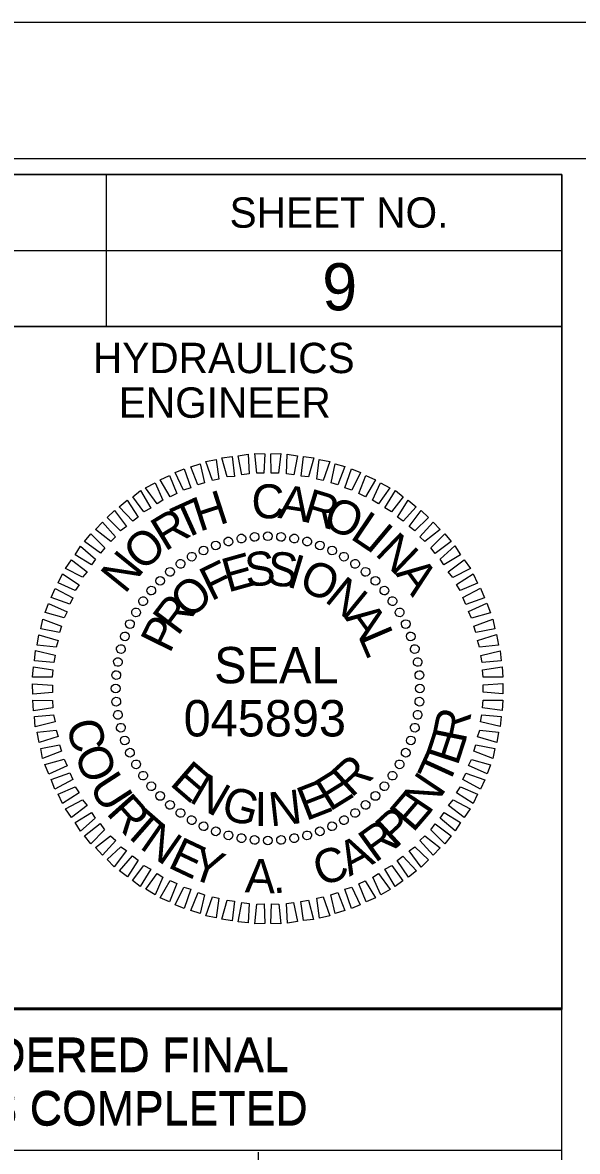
# Model space of a CAD drawing. Extents: x 1626113 to 1628102, y 900759 to 901859.
# Drawn here: x 1627691.2 to 1627782.5, y 901673.3 to 901859.2 of the extents above; entities that cross this region are included whole.
import ezdxf

# ---------------------------------------------------------------- set-up
doc = ezdxf.new("R2010")
doc.units = 0
for name, color, linetype in [('Default', 7, 'Continuous'), ('Sheet Cutting Line CELL', 7, 'Continuous'), ('Sheet Data Field CELL', 7, 'Continuous'), ('Sheet Plot Border Inside CELL', 7, 'Continuous'), ('Sheet Plot Border Outside CELL', 7, 'Continuous'), ('Sheet Profile CELL', 7, 'Continuous'), ('Sheet Profile Grid Major CELL', 7, 'Continuous'), ('Sheet Sticker Exception Certification CELL', 7, 'Continuous')]:
    doc.layers.add(name, color=color, linetype=linetype)

msp = doc.modelspace()

# ---------------------------------------------------------------- linework, layer by layer
at = {"layer": 'Default'}
for p, q in [((1627727.21, 901774.16), (1627727.21, 901774.16)), ((1627729.36, 901774.46), (1627729.36, 901774.46)), ((1627731.56, 901774.61), (1627731.56, 901774.61)), ((1627733.76, 901774.46), (1627733.76, 901774.46)), ((1627735.91, 901774.16), (1627735.91, 901774.16)), ((1627721.01, 901772.21), (1627721.01, 901772.21)), ((1627722.96, 901773.06), (1627722.96, 901773.06)), ((1627725.06, 901773.71), (1627725.06, 901773.71)), ((1627738.06, 901773.71), (1627738.06, 901773.71)), ((1627740.16, 901773.06), (1627740.16, 901773.06)), ((1627742.16, 901772.21), (1627742.16, 901772.21)), ((1627719.06, 901771.21), (1627719.06, 901771.21)), ((1627744.11, 901771.21), (1627744.11, 901771.21)), ((1627715.4, 901768.76), (1627715.4, 901768.76)), ((1627717.21, 901770.01), (1627717.21, 901770.01)), ((1627745.91, 901770.06), (1627745.91, 901770.06)), ((1627747.71, 901768.71), (1627747.71, 901768.71)), ((1627713.81, 901767.21), (1627713.81, 901767.21)), ((1627749.26, 901767.26), (1627749.26, 901767.26)), ((1627712.31, 901765.66), (1627712.31, 901765.66)), ((1627750.81, 901765.61), (1627750.81, 901765.61)), ((1627711.01, 901763.86), (1627711.01, 901763.86)), ((1627752.06, 901763.86), (1627752.06, 901763.86)), ((1627709.81, 901762.01), (1627709.81, 901762.01)), ((1627753.26, 901762.01), (1627753.26, 901762.01)), ((1627708.81, 901760.06), (1627708.81, 901760.06)), ((1627754.26, 901760.06), (1627754.26, 901760.06)), ((1627707.96, 901758.06), (1627707.96, 901758.06)), ((1627755.11, 901758.06), (1627755.11, 901758.06)), ((1627707.31, 901756.01), (1627707.31, 901756.01)), ((1627755.76, 901756.01), (1627755.76, 901756.01)), ((1627706.86, 901753.86), (1627706.86, 901753.86)), ((1627756.21, 901753.81), (1627756.21, 901753.81)), ((1627706.56, 901751.71), (1627706.56, 901751.71)), ((1627756.51, 901751.66), (1627756.51, 901751.66)), ((1627706.46, 901749.51), (1627706.46, 901749.51)), ((1627756.66, 901749.46), (1627756.66, 901749.46)), ((1627706.61, 901747.31), (1627706.61, 901747.31)), ((1627756.56, 901747.26), (1627756.56, 901747.26)), ((1627706.91, 901745.16), (1627706.91, 901745.16)), ((1627756.26, 901745.16), (1627756.26, 901745.16)), ((1627707.36, 901743.01), (1627707.36, 901743.01)), ((1627755.76, 901742.96), (1627755.76, 901742.96)), ((1627708.01, 901740.91), (1627708.01, 901740.91)), ((1627755.11, 901740.91), (1627755.11, 901740.91)), ((1627708.86, 901738.91), (1627708.86, 901738.91)), ((1627754.31, 901738.91), (1627754.31, 901738.91)), ((1627709.86, 901736.96), (1627709.86, 901736.96)), ((1627753.31, 901736.96), (1627753.31, 901736.96)), ((1627711.06, 901735.11), (1627711.06, 901735.11)), ((1627752.11, 901735.11), (1627752.11, 901735.11)), ((1627712.31, 901733.36), (1627712.31, 901733.36)), ((1627750.76, 901733.36), (1627750.76, 901733.36)), ((1627713.81, 901731.76), (1627713.81, 901731.76)), ((1627749.31, 901731.76), (1627749.31, 901731.76)), ((1627715.4, 901730.26), (1627715.4, 901730.26)), ((1627747.66, 901730.26), (1627747.66, 901730.26)), ((1627717.16, 901728.96), (1627717.16, 901728.96)), ((1627719.01, 901727.76), (1627719.01, 901727.76)), ((1627744.11, 901727.76), (1627744.11, 901727.76)), ((1627745.91, 901729.01), (1627745.91, 901729.01)), ((1627720.96, 901726.76), (1627720.96, 901726.76)), ((1627722.96, 901725.91), (1627722.96, 901725.91)), ((1627740.11, 901725.91), (1627740.11, 901725.91)), ((1627742.11, 901726.76), (1627742.11, 901726.76)), ((1627725.06, 901725.26), (1627725.06, 901725.26)), ((1627727.21, 901724.81), (1627727.21, 901724.81)), ((1627729.36, 901724.51), (1627729.36, 901724.51)), ((1627731.51, 901724.41), (1627731.51, 901724.41)), ((1627733.71, 901724.56), (1627733.71, 901724.56)), ((1627735.91, 901724.81), (1627735.91, 901724.81)), ((1627738.06, 901725.26), (1627738.06, 901725.26))]:
    msp.add_line(p, q, dxfattribs=at)
for points in [[(1627722.46, 901783.76), (1627721.36, 901786.91), (1627723.06, 901787.26), (1627723.51, 901784.01)], [(1627724.86, 901784.36), (1627724.01, 901787.51), (1627725.66, 901787.71), (1627726.06, 901784.46)], [(1627727.26, 901784.71), (1627726.66, 901787.86), (1627728.31, 901788.11), (1627728.46, 901784.86)], [(1627729.76, 901784.96), (1627729.41, 901788.21), (1627731.06, 901788.16), (1627730.91, 901784.96)], [(1627732.11, 901784.96), (1627732.06, 901788.16), (1627733.71, 901788.21), (1627733.31, 901784.96)], [(1627734.66, 901784.86), (1627734.76, 901788.11), (1627736.46, 901787.86), (1627735.86, 901784.71)], [(1627737.06, 901784.51), (1627737.46, 901787.71), (1627739.11, 901787.51), (1627738.26, 901784.36)], [(1627739.61, 901784.01), (1627740.01, 901787.26), (1627741.76, 901786.91), (1627740.66, 901783.76)], [(1627717.66, 901782.21), (1627716.31, 901785.11), (1627717.76, 901785.71), (1627718.86, 901782.56)], [(1627720.06, 901783.06), (1627718.86, 901786.01), (1627720.41, 901786.51), (1627721.11, 901783.41)], [(1627742.01, 901783.41), (1627742.66, 901786.51), (1627744.26, 901786.06), (1627743.06, 901783.06)], [(1627744.26, 901782.56), (1627745.36, 901785.71), (1627746.81, 901785.11), (1627745.41, 901782.21)], [(1627713.31, 901779.91), (1627711.41, 901782.56), (1627713.01, 901783.41), (1627714.26, 901780.51)], [(1627715.46, 901781.11), (1627713.81, 901783.91), (1627715.36, 901784.61), (1627716.56, 901781.61)], [(1627746.56, 901781.61), (1627747.71, 901784.61), (1627749.31, 901783.91), (1627747.66, 901781.11)], [(1627748.81, 901780.51), (1627750.11, 901783.41), (1627751.66, 901782.56), (1627749.81, 901779.96)], [(1627711.16, 901778.61), (1627709.31, 901781.11), (1627710.61, 901782.11), (1627712.31, 901779.21)], [(1627750.81, 901779.26), (1627752.56, 901782.11), (1627753.86, 901781.11), (1627751.91, 901778.61)], [(1627709.31, 901777.06), (1627707.06, 901779.46), (1627708.41, 901780.51), (1627710.21, 901777.76)], [(1627752.91, 901777.76), (1627754.66, 901780.51), (1627756.01, 901779.46), (1627753.86, 901777.06)], [(1627707.31, 901775.51), (1627705.11, 901777.66), (1627706.31, 901778.86), (1627708.26, 901776.21)], [(1627754.81, 901776.21), (1627756.81, 901778.86), (1627758.01, 901777.66), (1627755.76, 901775.51)], [(1627705.71, 901773.71), (1627703.16, 901775.71), (1627704.36, 901776.91), (1627706.46, 901774.51)], [(1627756.61, 901774.51), (1627758.76, 901776.91), (1627759.96, 901775.71), (1627757.41, 901773.71)], [(1627704.01, 901771.81), (1627701.36, 901773.71), (1627702.41, 901775.01), (1627704.71, 901772.71)], [(1627758.41, 901772.71), (1627760.71, 901775.01), (1627761.76, 901773.71), (1627759.11, 901771.76)], [(1627702.51, 901769.86), (1627699.81, 901771.56), (1627700.71, 901772.96), (1627703.16, 901770.81)], [(1627759.96, 901770.81), (1627762.36, 901773.01), (1627763.31, 901771.56), (1627760.56, 901769.86)], [(1627701.06, 901767.86), (1627698.26, 901769.26), (1627699.21, 901770.71), (1627701.81, 901768.76)], [(1627761.26, 901768.76), (1627763.91, 901770.71), (1627764.91, 901769.26), (1627762.01, 901767.81)], [(1627699.86, 901765.66), (1627697.01, 901766.91), (1627697.76, 901768.41), (1627700.51, 901766.61)], [(1627762.61, 901766.66), (1627765.36, 901768.41), (1627766.06, 901766.86), (1627763.21, 901765.66)], [(1627698.96, 901763.41), (1627695.86, 901764.51), (1627696.56, 901766.01), (1627699.46, 901764.46)], [(1627763.66, 901764.51), (1627766.56, 901766.06), (1627767.26, 901764.46), (1627764.16, 901763.36)], [(1627698.01, 901761.16), (1627694.91, 901762.01), (1627695.46, 901763.51), (1627698.51, 901762.16)], [(1627764.61, 901762.21), (1627767.61, 901763.56), (1627768.21, 901761.96), (1627765.11, 901761.11)], [(1627697.26, 901758.76), (1627694.16, 901759.36), (1627694.51, 901760.96), (1627697.61, 901759.76)], [(1627765.46, 901759.76), (1627768.61, 901760.96), (1627768.96, 901759.36), (1627765.81, 901758.76)], [(1627696.71, 901756.31), (1627693.56, 901756.66), (1627693.86, 901758.36), (1627697.01, 901757.41)], [(1627766.06, 901757.41), (1627769.21, 901758.41), (1627769.56, 901756.66), (1627766.41, 901756.31)], [(1627696.31, 901753.81), (1627693.11, 901754.06), (1627693.31, 901755.76), (1627696.56, 901755.01)], [(1627766.61, 901754.96), (1627769.81, 901755.71), (1627770.01, 901754.06), (1627766.86, 901753.81)], [(1627696.06, 901751.36), (1627692.81, 901751.36), (1627692.96, 901753.06), (1627696.16, 901752.61)], [(1627766.91, 901752.61), (1627770.16, 901753.11), (1627770.26, 901751.41), (1627767.01, 901751.41)], [(1627696.11, 901748.86), (1627692.86, 901748.61), (1627692.81, 901750.31), (1627696.11, 901750.06)], [(1627767.01, 901750.11), (1627770.26, 901750.36), (1627770.26, 901748.66), (1627767.01, 901748.91)], [(1627696.16, 901746.36), (1627692.96, 901745.86), (1627692.86, 901747.61), (1627696.11, 901747.56)], [(1627767.01, 901747.61), (1627770.26, 901747.61), (1627770.16, 901745.91), (1627766.91, 901746.36)], [(1627696.56, 901744.01), (1627693.26, 901743.21), (1627693.11, 901744.91), (1627696.26, 901745.16)], [(1627766.81, 901745.16), (1627770.01, 901744.91), (1627769.81, 901743.26), (1627766.56, 901744.01)], [(1627697.06, 901741.61), (1627693.91, 901740.61), (1627693.56, 901742.31), (1627696.71, 901742.66)], [(1627766.46, 901742.66), (1627769.56, 901742.31), (1627769.26, 901740.61), (1627766.11, 901741.56)], [(1627697.61, 901739.21), (1627694.46, 901738.01), (1627694.16, 901739.66), (1627697.26, 901740.26)], [(1627765.81, 901740.26), (1627768.96, 901739.66), (1627768.61, 901738.01), (1627765.46, 901739.21)], [(1627698.51, 901736.76), (1627695.51, 901735.41), (1627694.86, 901737.01), (1627698.01, 901737.86)], [(1627765.11, 901737.81), (1627768.21, 901736.96), (1627767.66, 901735.46), (1627764.61, 901736.81)], [(1627699.46, 901734.51), (1627696.51, 901732.96), (1627695.86, 901734.51), (1627698.96, 901735.61)], [(1627764.16, 901735.56), (1627767.31, 901734.46), (1627766.56, 901732.96), (1627763.66, 901734.51)], [(1627700.51, 901732.36), (1627697.76, 901730.56), (1627697.01, 901732.11), (1627699.86, 901733.31)], [(1627763.26, 901733.31), (1627766.06, 901732.11), (1627765.36, 901730.56), (1627762.61, 901732.36)], [(1627701.81, 901730.26), (1627699.21, 901728.26), (1627698.26, 901729.71), (1627701.06, 901731.16)], [(1627762.06, 901731.16), (1627764.86, 901729.71), (1627763.91, 901728.26), (1627761.31, 901730.26)], [(1627703.11, 901728.16), (1627700.71, 901726.01), (1627699.81, 901727.46), (1627702.51, 901729.11)], [(1627760.61, 901729.11), (1627763.31, 901727.46), (1627762.41, 901726.06), (1627759.96, 901728.16)], [(1627704.66, 901726.26), (1627702.41, 901723.96), (1627701.36, 901725.26), (1627703.96, 901727.26)], [(1627759.11, 901727.21), (1627761.76, 901725.26), (1627760.71, 901723.96), (1627758.41, 901726.26)], [(1627706.51, 901724.46), (1627704.31, 901722.06), (1627703.16, 901723.31), (1627705.66, 901725.26)], [(1627757.41, 901725.26), (1627759.96, 901723.26), (1627758.76, 901722.06), (1627756.61, 901724.46)], [(1627708.31, 901722.81), (1627706.26, 901720.16), (1627705.11, 901721.36), (1627707.36, 901723.46)], [(1627710.21, 901721.26), (1627708.46, 901718.51), (1627707.11, 901719.51), (1627709.26, 901721.96)], [(1627753.81, 901721.91), (1627756.06, 901719.51), (1627754.71, 901718.46), (1627752.86, 901721.21)], [(1627755.76, 901723.46), (1627758.01, 901721.31), (1627756.81, 901720.11), (1627754.86, 901722.76)], [(1627712.31, 901719.76), (1627710.56, 901716.91), (1627709.26, 901717.91), (1627711.16, 901720.36)], [(1627751.96, 901720.36), (1627753.81, 901717.86), (1627752.51, 901716.91), (1627750.81, 901719.76)], [(1627714.26, 901718.46), (1627713.01, 901715.56), (1627711.46, 901716.46), (1627713.31, 901719.06)], [(1627749.76, 901719.06), (1627751.71, 901716.41), (1627750.16, 901715.56), (1627748.86, 901718.46)], [(1627716.56, 901717.41), (1627715.36, 901714.36), (1627713.81, 901715.06), (1627715.46, 901717.91)], [(1627718.86, 901716.46), (1627717.76, 901713.31), (1627716.31, 901713.86), (1627717.71, 901716.81)], [(1627745.41, 901716.81), (1627746.76, 901713.86), (1627745.36, 901713.31), (1627744.26, 901716.46)], [(1627747.61, 901717.86), (1627749.31, 901715.06), (1627747.76, 901714.36), (1627746.56, 901717.36)], [(1627721.11, 901715.56), (1627720.41, 901712.46), (1627718.86, 901712.96), (1627720.11, 901715.91)], [(1627723.51, 901714.96), (1627723.06, 901711.76), (1627721.36, 901712.06), (1627722.46, 901715.21)], [(1627726.06, 901714.51), (1627725.66, 901711.26), (1627724.01, 901711.51), (1627724.86, 901714.66)], [(1627738.26, 901714.66), (1627739.06, 901711.46), (1627737.41, 901711.31), (1627737.01, 901714.46)], [(1627740.66, 901715.21), (1627741.76, 901712.06), (1627740.06, 901711.71), (1627739.61, 901714.96)], [(1627743.06, 901715.91), (1627744.26, 901712.96), (1627742.66, 901712.46), (1627741.96, 901715.56)], [(1627728.46, 901714.11), (1627728.31, 901710.91), (1627726.66, 901711.11), (1627727.26, 901714.26)], [(1627730.96, 901714.06), (1627731.06, 901710.81), (1627729.41, 901710.76), (1627729.76, 901714.01)], [(1627733.36, 901714.01), (1627733.71, 901710.76), (1627732.06, 901710.81), (1627732.16, 901714.06)], [(1627735.81, 901714.26), (1627736.46, 901711.16), (1627734.81, 901710.86), (1627734.66, 901714.11)]]:
    msp.add_lwpolyline(points, close=True, dxfattribs=at)
for centre, major_axis in [((1627725.07, 901773.73), (-0.186, 0.695)), ((1627727.21, 901774.21), (-0.125, 0.708)), ((1627729.37, 901774.49), (-0.063, 0.717)), ((1627731.56, 901774.59), (0, 0.719)), ((1627733.74, 901774.49), (0.063, 0.717)), ((1627735.91, 901774.21), (0.125, 0.708)), ((1627738.04, 901773.73), (0.186, 0.695)), ((1627720.97, 901772.24), (-0.304, 0.652)), ((1627722.99, 901773.08), (-0.246, 0.676)), ((1627740.13, 901773.08), (0.246, 0.676)), ((1627742.15, 901772.24), (0.304, 0.652)), ((1627717.19, 901770.06), (-0.413, 0.589)), ((1627719.03, 901771.23), (-0.36, 0.623)), ((1627744.09, 901771.23), (0.36, 0.623)), ((1627745.93, 901770.06), (0.413, 0.589)), ((1627715.45, 901768.73), (-0.462, 0.551)), ((1627747.66, 901768.73), (0.462, 0.551)), ((1627713.84, 901767.25), (-0.509, 0.509)), ((1627749.27, 901767.25), (0.509, 0.509)), ((1627711.03, 901763.9), (-0.589, 0.413)), ((1627712.36, 901765.64), (-0.551, 0.462)), ((1627750.75, 901765.64), (0.551, 0.462)), ((1627752.08, 901763.9), (0.589, 0.413)), ((1627709.86, 901762.06), (-0.623, 0.36)), ((1627753.26, 901762.06), (0.623, 0.36)), ((1627708.85, 901760.12), (-0.652, 0.304)), ((1627754.27, 901760.12), (0.652, 0.304)), ((1627708.01, 901758.1), (-0.676, 0.246)), ((1627755.1, 901758.1), (0.676, 0.246)), ((1627707.36, 901756.02), (-0.695, 0.186)), ((1627755.76, 901756.02), (0.695, 0.186)), ((1627706.88, 901753.88), (-0.708, 0.125)), ((1627756.23, 901753.88), (0.708, 0.125)), ((1627706.6, 901751.72), (-0.717, 0.063)), ((1627756.52, 901751.72), (0.717, 0.063)), ((1627706.5, 901749.53), (-0.719, 0)), ((1627756.61, 901749.53), (0.719, 0)), ((1627706.6, 901747.35), (-0.717, -0.063)), ((1627756.52, 901747.35), (0.717, -0.063)), ((1627706.88, 901745.18), (-0.708, -0.125)), ((1627756.23, 901745.18), (0.708, -0.125)), ((1627707.36, 901743.05), (-0.695, -0.186)), ((1627755.76, 901743.05), (0.695, -0.186)), ((1627708.01, 901740.96), (-0.676, -0.246)), ((1627755.1, 901740.96), (0.676, -0.246)), ((1627708.85, 901738.95), (-0.652, -0.304)), ((1627754.27, 901738.95), (0.652, -0.304)), ((1627709.86, 901737.01), (-0.623, -0.36)), ((1627753.26, 901737.01), (0.623, -0.36)), ((1627711.03, 901735.16), (-0.589, -0.413)), ((1627752.08, 901735.16), (0.589, -0.413)), ((1627712.36, 901733.43), (-0.551, -0.462)), ((1627750.75, 901733.43), (0.551, -0.462)), ((1627713.84, 901731.82), (-0.509, -0.509)), ((1627749.27, 901731.82), (0.509, -0.509)), ((1627715.45, 901730.34), (-0.462, -0.551)), ((1627717.19, 901729.01), (-0.413, -0.589)), ((1627745.93, 901729.01), (0.413, -0.589)), ((1627747.66, 901730.34), (0.462, -0.551)), ((1627719.03, 901727.84), (-0.36, -0.623)), ((1627720.97, 901726.83), (-0.304, -0.652)), ((1627742.15, 901726.83), (0.304, -0.652)), ((1627744.09, 901727.84), (0.36, -0.623)), ((1627722.99, 901725.99), (-0.246, -0.676)), ((1627725.07, 901725.33), (-0.186, -0.695)), ((1627727.21, 901724.86), (-0.125, -0.708)), ((1627735.91, 901724.86), (0.125, -0.708)), ((1627738.04, 901725.33), (0.186, -0.695)), ((1627740.13, 901725.99), (0.246, -0.676)), ((1627729.37, 901724.57), (-0.063, -0.717)), ((1627731.56, 901724.48), (0, -0.719)), ((1627733.74, 901724.57), (0.063, -0.717))]:
    msp.add_ellipse(centre, major_axis=major_axis, ratio=0.999708, dxfattribs=at)
at = {"layer": 'Sheet Cutting Line CELL'}
msp.add_line((1627796.95, 901859.2), (1626112.95, 901859.2), dxfattribs=at)
at = {"layer": 'Sheet Plot Border Inside CELL'}
msp.add_lwpolyline([(1626125.95, 900781.65), (1627792.45, 900781.65), (1627792.45, 901836.75), (1626125.95, 901836.75)], close=True, dxfattribs=at)
at = {"layer": 'Sheet Plot Border Outside CELL'}
msp.add_lwpolyline([(1626112.95, 900759.2), (1627796.95, 900759.2), (1627796.95, 901859.2), (1626112.95, 901859.2)], close=True, dxfattribs=at)
at = {"layer": 'Sheet Profile CELL'}
for p, q in [((1627704.95, 901834.15), (1627704.95, 901809.15)), ((1627579.9, 901821.65), (1627779.95, 901821.65))]:
    msp.add_line(p, q, dxfattribs=at)
for points in [[(1627779.95, 901834.2), (1626279.95, 901834.2), (1626279.95, 900784.2), (1627779.95, 900784.2)], [(1627579.9, 901834.2), (1627779.95, 901834.2), (1627779.95, 901809.15), (1627579.9, 901809.15)], [(1627679.95, 901809.15), (1627779.95, 901809.15), (1627779.95, 901696.65), (1627679.95, 901696.65)]]:
    msp.add_lwpolyline(points, close=True, dxfattribs=at)
at = {"layer": 'Sheet Profile Grid Major CELL'}
msp.add_lwpolyline([(1627729.95, 901673.15), (1627729.95, 901334.2), (1627779.95, 901334.2), (1627779.95, 901684.2)], dxfattribs=at)
at = {"layer": 'Sheet Sticker Exception Certification CELL'}
for p, q in [((1627579.9, 901696.9), (1627779.93, 901696.9)), ((1627579.9, 901696.9), (1627779.93, 901696.9)), ((1627579.9, 901696.65), (1627779.93, 901696.65)), ((1627579.9, 901696.65), (1627779.93, 901696.65)), ((1627779.93, 901696.89), (1627779.93, 901673.39)), ((1627779.93, 901696.89), (1627779.93, 901673.39)), ((1627779.93, 901696.64), (1627779.93, 901673.14)), ((1627779.93, 901696.64), (1627779.93, 901673.14)), ((1627779.93, 901673.4), (1627579.9, 901673.4)), ((1627779.93, 901673.4), (1627579.9, 901673.4))]:
    msp.add_line(p, q, dxfattribs=at)

# ---------------------------------------------------------------- texts
at = {"layer": 'Default'}
for s, height, rotation, p in [('C', 5.6, 359.8514, (1627728.86, 901777.55)), ('H', 5.6, 17.9268, (1627720.28, 901775.32)), ('A', 5.6, 351.2223, (1627733.1, 901777.64)), ('R', 5.6, 343.1874, (1627737.02, 901777.15)), ('T', 5.6, 24.3275, (1627717.47, 901773.89)), ('O', 5.6, 336.242, (1627740.32, 901776.29)), ('R', 5.6, 31.2729, (1627714.62, 901772.01)), ('L', 5.6, 326.0282, (1627744.94, 901774.32)), ('I', 5.6, 320.0485, (1627747.45, 901772.79)), ('O', 5.6, 41.4867, (1627710.9, 901768.64)), ('N', 5.6, 316.0496, (1627749.04, 901771.63)), ('N', 5.6, 51.032, (1627708.01, 901764.95)), ('S', 5.6, 5.0487, (1627728, 901766.25)), ('S', 5.6, 354.1866, (1627731.23, 901766.62)), ('F', 5.6, 26.1465, (1627722.21, 901763.83)), ('E', 5.6, 15.6529, (1627724.98, 901765.3)), ('I', 5.6, 343.3245, (1627734.46, 901766.38)), ('O', 5.6, 336.6634, (1627736.4, 901765.93)), ('A', 5.6, 306.5043, (1627752.47, 901768.43)), ('O', 5.6, 42.0574, (1627718.63, 901760.71)), ('N', 5.6, 320.7526, (1627740.73, 901763.98)), ('R', 5.6, 53.1038, (1627716.72, 901758.02)), ('P', 5.6, 63.7079, (1627715.4, 901755.14)), ('A', 5.6, 305.8367, (1627744.15, 901761.14)), ('L', 5.6, 293.1688, (1627746.41, 901758.1)), ('SEAL', 5.992, 360, (1627722.71, 901750.37)), ('045893', 5.994, 360, (1627717.69, 901741.62)), ('R', 5.6, 78.5969, (1627764.08, 901740.34)), ('C', 5.6, 284.0401, (1627698.32, 901743.78)), ('E', 5.6, 71.9487, (1627762.8, 901736.64)), ('O', 5.6, 292.6692, (1627699.55, 901738.85)), ('T', 5.6, 65.548, (1627761.18, 901733.24)), ('E', 5.6, 319.2324, (1627715.23, 901733.72)), ('R', 5.6, 42.4535, (1627745.31, 901731.39)), ('U', 5.6, 302.883, (1627701.95, 901733.34)), ('N', 5.6, 329.8366, (1627718.41, 901730.98)), ('E', 5.6, 31.8494, (1627741.74, 901729.17)), ('N', 5.6, 56.0027, (1627758.07, 901728.56)), ('G', 5.6, 344.7525, (1627723.62, 901728.22)), ('E', 5.6, 21.2452, (1627737.83, 901727.65)), ('R', 5.6, 311.7969, (1627704.8, 901728.94)), ('I', 5.6, 359.6683, (1627729.36, 901726.88)), ('N', 5.6, 6.3293, (1627732, 901726.78)), ('E', 5.6, 49.3544, (1627755.47, 901725.64)), ('T', 5.6, 318.7423, (1627707.49, 901725.85)), ('P', 5.6, 42.7062, (1627752.55, 901723.03)), ('N', 5.6, 325.143, (1627710.27, 901723.31)), ('R', 5.6, 35.7608, (1627749.2, 901720.69)), ('E', 5.6, 334.6883, (1627714.9, 901720.14)), ('A', 5.6, 27.7259, (1627745, 901718.51)), ('Y', 5.6, 341.3366, (1627718.41, 901718.41)), ('C', 5.6, 19.0968, (1627740.2, 901716.85)), ('A', 5.6, 357.753, (1627727.73, 901715.95)), ('.', 5.6, 5.7878, (1627732.46, 901715.74))]:
    msp.add_text(s, height=height, rotation=rotation, dxfattribs=at).set_placement(p)
at = {"layer": 'Sheet Data Field CELL'}
msp.add_text('9', height=7.75, dxfattribs=at).set_placement((1627740.51, 901811.81))
at = {"layer": 'Sheet Profile CELL'}
for s, p in [('SHEET NO.', (1627725.26, 901825.41)), ('HYDRAULICS', (1627702.76, 901801.46)), ('ENGINEER', (1627707.01, 901794.11))]:
    msp.add_text(s, height=5, dxfattribs=at).set_placement(p)
at = {"layer": 'Sheet Sticker Exception Certification CELL'}
for s, p in [('DOCUMENT NOT CONSIDERED FINAL', (1627600.97, 901686.55)), ('DOCUMENT NOT CONSIDERED FINAL', (1627600.97, 901686.55)), ('DOCUMENT NOT CONSIDERED FINAL', (1627600.97, 901686.3)), ('DOCUMENT NOT CONSIDERED FINAL', (1627600.97, 901686.3)), ('UNLESS ALL SIGNATURES COMPLETED', (1627595.9, 901677.75)), ('UNLESS ALL SIGNATURES COMPLETED', (1627595.9, 901677.75)), ('UNLESS ALL SIGNATURES COMPLETED', (1627595.9, 901677.5)), ('UNLESS ALL SIGNATURES COMPLETED', (1627595.9, 901677.5))]:
    msp.add_text(s, height=5.5, dxfattribs=at).set_placement(p)

doc.saveas('drawing.dxf')
